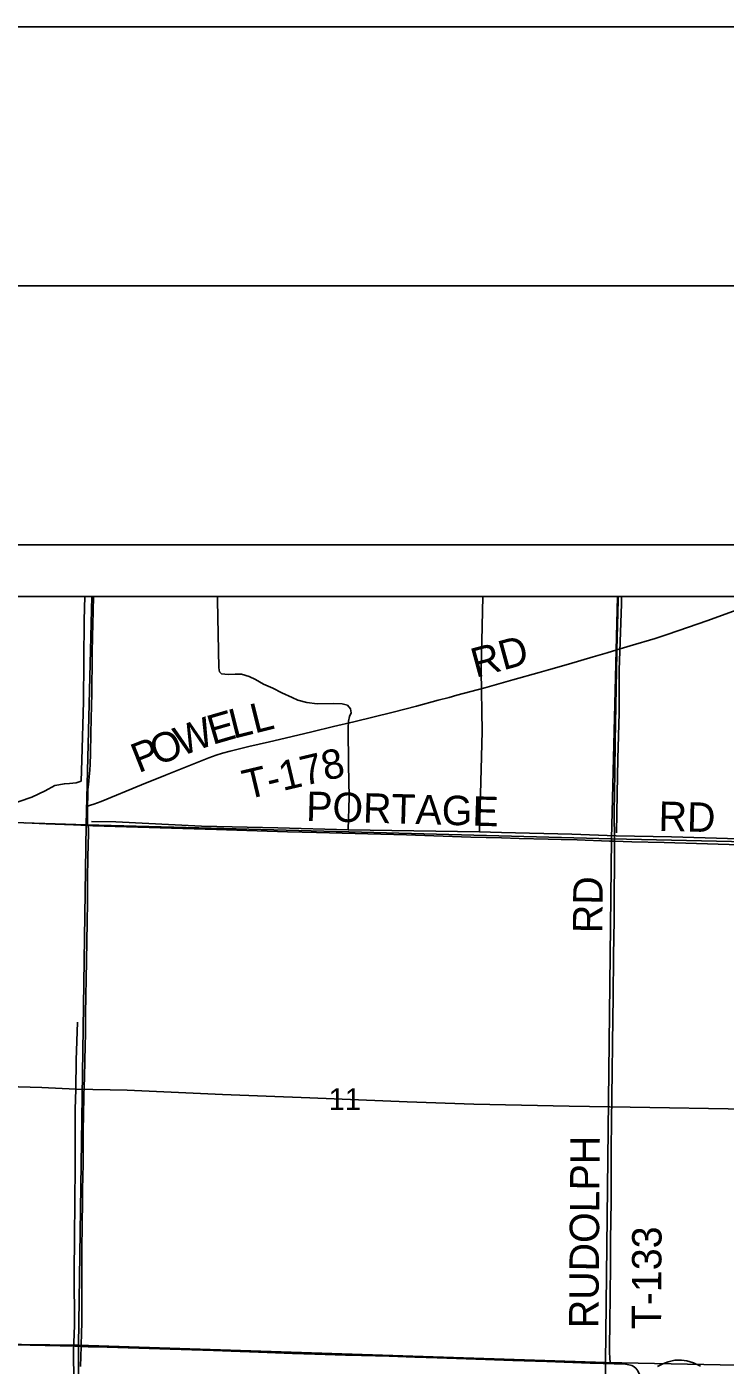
# Model space of a CAD drawing. Extents: x 0 to 39.4, y 0 to 22.
# Drawn here: x 3.277 to 4.625, y 19.416 to 22 of the extents above; entities that cross this region are included whole.
import ezdxf

# ---------------------------------------------------------------- set-up
doc = ezdxf.new("R2010")
doc.units = 0
for name, color, linetype in [('Default', 7, 'Continuous'), ('GM_X_Interstate_Route', 7, 'Continuous'), ('GM_X_Major_River', 7, 'Continuous'), ('GM_X_Minor_River', 7, 'Continuous'), ('GM_X_Section', 7, 'Continuous'), ('GM_X_Section_Text', 7, 'Continuous'), ('GM_X_Township_Road', 7, 'Continuous'), ('GM_X_Township_Road_Text', 7, 'Continuous'), ('SH_Border', 7, 'Continuous'), ('SH_Cut_Line', 7, 'Continuous'), ('SH_Data', 7, 'Continuous')]:
    doc.layers.add(name, color=color, linetype=linetype)

msp = doc.modelspace()

# ---------------------------------------------------------------- linework, layer by layer
at = {"layer": 'Default'}
for points in [[(3.4024, 20.9), (2.3931, 20.9), (2.3906, 20.4913), (3.3917, 20.4596)], [(4.4171, 20.9), (3.4024, 20.9), (3.3917, 20.4596), (4.4054, 20.4323)], [(5.4307, 20.9), (4.4171, 20.9), (4.4054, 20.4323), (5.4199, 20.4099)]]:
    msp.add_lwpolyline(points, close=True, dxfattribs=at)
at = {"layer": 'GM_X_Interstate_Route'}
msp.add_lwpolyline([(5.4327, 20.9), (2.1, 20.9)], dxfattribs=at)
at = {"layer": 'GM_X_Major_River'}
msp.add_lwpolyline([(4.5772, 19.4146), (4.5636, 19.4211), (4.5507, 19.4246), (4.5408, 19.4257), (4.5279, 19.4258), (4.515, 19.4228), (4.5048, 19.4186), (4.4941, 19.4137)], dxfattribs=at)
at = {"layer": 'GM_X_Minor_River'}
for points in [[(3.3893, 20.9), (3.3877, 20.8543), (3.3868, 20.6974), (3.3835, 20.5843), (3.3818, 20.544), (3.3723, 20.5406), (3.3594, 20.5391), (3.3496, 20.5388), (3.3313, 20.535), (3.3123, 20.5248), (3.2869, 20.5128), (3.2626, 20.5045), (3.2424, 20.4977), (3.228, 20.4905), (3.2071, 20.4769), (3.1965, 20.4762), (2.9935, 20.4806), (2.8319, 20.4845), (2.7583, 20.4866), (2.5868, 20.4939), (2.399, 20.4979)], [(3.8975, 20.4498), (3.8989, 20.5128), (3.8979, 20.5755), (3.897, 20.6469), (3.8978, 20.6594), (3.8997, 20.6682), (3.9028, 20.6754), (3.9017, 20.683), (3.8957, 20.6906), (3.8858, 20.6929), (3.8691, 20.6937), (3.8376, 20.693), (3.8175, 20.6958), (3.8004, 20.7), (3.7894, 20.705), (3.7693, 20.7145), (3.7519, 20.7229), (3.7341, 20.731), (3.7182, 20.7398), (3.7061, 20.7455), (3.6917, 20.7501), (3.6792, 20.7505), (3.6655, 20.7498), (3.6526, 20.751), (3.6488, 20.7548), (3.6477, 20.7624), (3.6451, 20.8934), (3.6452, 20.9)], [(4.1506, 20.4456), (4.1557, 20.6397), (4.1542, 20.7567), (4.157, 20.9)], [(4.425, 20.9), (4.4248, 20.8861), (4.4223, 20.8125), (4.4202, 20.7578), (4.4203, 20.6757), (4.4178, 20.5868), (4.4164, 20.5192), (4.415, 20.444)], [(5.0405, 20.629), (5.0417, 20.5162), (5.0429, 20.4182), (4.9063, 20.4236), (4.7159, 20.4302), (4.5213, 20.4361), (4.4146, 20.4383), (4.3289, 20.4412), (4.1931, 20.4443), (4.1506, 20.4456), (3.8975, 20.4498), (3.7617, 20.4536), (3.6141, 20.4571), (3.4491, 20.4655), (3.4017, 20.4657)], [(2.8819, 20.2127), (2.8805, 20.1337), (2.8805, 20.03), (2.8792, 19.9628), (2.9205, 19.9619), (3.0951, 19.9588), (3.2157, 19.955), (3.3064, 19.9524), (3.3716, 19.9492), (3.4706, 19.947), (3.655, 19.9389), (3.8234, 19.9323), (4.0109, 19.9245), (4.1395, 19.9203), (4.3235, 19.916), (4.4418, 19.9145), (4.6683, 19.9107), (4.8691, 19.9098), (4.9609, 19.9087), (5.0834, 19.9068), (5.1464, 19.9048), (5.2027, 19.9034)], [(3.3676, 19.3853), (3.367, 19.4425), (3.3691, 19.4938), (3.3686, 19.5948), (3.3692, 19.6632), (3.3704, 19.7995), (3.3707, 19.9101), (3.3716, 19.9492), (3.3726, 20.005), (3.3751, 20.0783)]]:
    msp.add_lwpolyline(points, dxfattribs=at)
at = {"layer": 'GM_X_Section'}
for points in [[(2.3906, 20.4913), (3.3917, 20.4596), (3.377, 19.4549), (2.7709, 19.4617), (2.3842, 19.4785)], [(3.3917, 20.4596), (4.4054, 20.4323), (4.394, 19.4215), (3.377, 19.4549)], [(4.4054, 20.4323), (5.4199, 20.4099), (5.4196, 20.3595), (5.4059, 19.4006), (4.394, 19.4215)], [(2.3842, 19.4785), (2.7709, 19.4617), (3.377, 19.4549), (3.3817, 18.4522), (2.3742, 18.4805)], [(3.377, 19.4549), (4.394, 19.4215), (4.3942, 18.4237), (3.3817, 18.4522)], [(4.394, 19.4215), (5.4059, 19.4006), (5.4065, 19.3604), (5.3953, 18.3924), (4.3942, 18.4237)]]:
    msp.add_lwpolyline(points, close=True, dxfattribs=at)
at = {"layer": 'GM_X_Township_Road'}
for points in [[(3.3945, 20.4952), (3.3945, 20.4963), (3.3948, 20.5151), (3.3952, 20.5268), (3.3959, 20.5371), (3.3974, 20.552), (3.3985, 20.565), (3.3992, 20.5768), (3.3999, 20.5967), (3.4008, 20.6364), (3.4021, 20.6905), (3.4025, 20.7117), (3.4028, 20.7347), (3.4032, 20.7632), (3.4035, 20.79), (3.4042, 20.8242), (3.4047, 20.8453), (3.4056, 20.9)], [(4.416, 20.7972), (4.4168, 20.8442), (4.4181, 20.8939), (4.4183, 20.9)], [(4.416, 20.7972), (4.4418, 20.8048), (4.4895, 20.8191), (4.5131, 20.8267), (4.5543, 20.8409), (4.5895, 20.8532), (4.6975, 20.8926), (4.7122, 20.8976), (4.7188, 20.9)], [(3.3945, 20.4952), (3.4003, 20.4971), (3.4062, 20.4991), (3.4207, 20.5046), (3.4984, 20.5364), (3.5445, 20.5551), (3.6282, 20.5885), (3.6428, 20.5939), (3.6546, 20.5977), (3.6696, 20.6017), (3.7059, 20.6105), (3.7453, 20.6194), (3.7755, 20.6266), (3.8269, 20.6388), (3.8692, 20.649), (3.9085, 20.6583), (3.984, 20.6768), (4.0291, 20.6884), (4.0711, 20.6998), (4.0922, 20.7052), (4.1071, 20.7095), (4.1611, 20.724), (4.2149, 20.7393), (4.2659, 20.7533), (4.2838, 20.7584), (4.3225, 20.7698), (4.3703, 20.7836), (4.3971, 20.7917), (4.416, 20.7972)], [(4.411, 20.4277), (4.4107, 20.4836), (4.4112, 20.5209), (4.4117, 20.5613), (4.4125, 20.6204), (4.4146, 20.7229), (4.4159, 20.7913), (4.416, 20.7972)], [(3.395, 20.458), (3.3945, 20.4606), (3.3942, 20.4622), (3.3941, 20.4632), (3.3941, 20.4642), (3.3945, 20.4952)], [(3.274, 20.4632), (3.3144, 20.4613), (3.3671, 20.4591), (3.395, 20.458)], [(3.3818, 19.4524), (3.3818, 19.4543), (3.3825, 19.4788), (3.383, 19.4976), (3.3833, 19.5056), (3.3832, 19.5392), (3.3834, 19.569), (3.3835, 19.6057), (3.3835, 19.6318), (3.384, 19.6952), (3.3844, 19.7254), (3.3849, 19.7579), (3.3852, 19.7773), (3.3857, 19.8071), (3.3858, 19.8189), (3.386, 19.8438), (3.386, 19.8718), (3.3863, 19.8972), (3.387, 19.9377), (3.3884, 19.9718), (3.3893, 20.0041), (3.3898, 20.0327), (3.3902, 20.0557), (3.3907, 20.0955), (3.3912, 20.1272), (3.3917, 20.1633), (3.3921, 20.195), (3.3929, 20.2366), (3.3934, 20.2683), (3.394, 20.3131), (3.3945, 20.3535), (3.3952, 20.3982), (3.3957, 20.4194), (3.3959, 20.443), (3.3959, 20.453), (3.3959, 20.4538), (3.3957, 20.4547), (3.3956, 20.4555), (3.395, 20.458)], [(3.395, 20.458), (3.4044, 20.4577), (3.6435, 20.4504), (3.7802, 20.4459), (3.8361, 20.4446), (3.9603, 20.4412), (4.01, 20.4398), (4.0628, 20.4381), (4.1342, 20.4358), (4.1932, 20.434), (4.2274, 20.4333), (4.2833, 20.4316), (4.3082, 20.4309), (4.3392, 20.4302), (4.4013, 20.428), (4.411, 20.4277)], [(4.4037, 19.4193), (4.4031, 19.4233), (4.4025, 19.4282), (4.4021, 19.4327), (4.4017, 19.439), (4.4018, 19.4545), (4.4024, 19.495), (4.4029, 19.554), (4.4033, 19.6069), (4.4038, 19.6566), (4.4042, 19.697), (4.4046, 19.7312), (4.4049, 19.7965), (4.4051, 19.8338), (4.4055, 19.8867), (4.4067, 19.983), (4.4072, 20.0359), (4.4079, 20.0856), (4.4085, 20.126), (4.4095, 20.2069), (4.4104, 20.2753), (4.4107, 20.3188), (4.4112, 20.3903), (4.411, 20.4277)], [(4.411, 20.4277), (4.4448, 20.4267), (4.5069, 20.425), (4.6529, 20.4205), (4.7492, 20.4177), (4.7926, 20.4164), (4.833, 20.4154), (4.9045, 20.4137), (4.9112, 20.4137)], [(2.3844, 19.4813), (2.3919, 19.4813), (2.4199, 19.4804), (2.4727, 19.4781), (2.5161, 19.4762), (2.572, 19.474), (2.6186, 19.4719), (2.6869, 19.469), (2.7801, 19.4654), (2.8453, 19.4635), (2.895, 19.4619), (2.9602, 19.4607), (2.9975, 19.46), (3.0348, 19.4594), (3.1249, 19.4576), (3.1684, 19.4567), (3.2088, 19.4559), (3.2834, 19.4546), (3.3704, 19.4527), (3.3818, 19.4524)], [(3.3806, 19.4139), (3.3818, 19.4524)], [(3.3818, 19.4524), (3.3958, 19.452), (3.4325, 19.451), (3.4729, 19.4499), (3.5537, 19.4471), (3.6375, 19.4445), (3.6717, 19.4435), (3.7245, 19.4415), (3.7897, 19.439), (3.8332, 19.4376), (3.8922, 19.4358), (3.9233, 19.4349), (3.9761, 19.4335), (4.0258, 19.4317), (4.0693, 19.4304), (4.1066, 19.4293), (4.1625, 19.4273), (4.2153, 19.4255), (4.2805, 19.4233), (4.3643, 19.4203), (4.3892, 19.4194), (4.4037, 19.4193)], [(4.4037, 19.4193), (4.4109, 19.4192), (4.4234, 19.4186), (4.4322, 19.418), (4.4388, 19.4171), (4.4419, 19.4165), (4.4448, 19.4155), (4.4476, 19.4141), (4.4501, 19.4123), (4.4524, 19.4103), (4.4544, 19.4079), (4.4561, 19.4053), (4.4577, 19.4024), (4.4606, 19.3968), (4.4629, 19.3922), (4.464, 19.3897), (4.4649, 19.3875)]]:
    msp.add_lwpolyline(points, dxfattribs=at)
at = {"layer": 'SH_Border'}
msp.add_lwpolyline([(1.5, 21.5), (33.5, 21.5), (33.5, 0.5), (1.5, 0.5)], close=True, dxfattribs=at)
at = {"layer": 'SH_Cut_Line'}
msp.add_lwpolyline([(0, 0), (34, 0), (34, 22), (0, 22)], close=True, dxfattribs=at)
at = {"layer": 'SH_Data'}
for p, q in [((2, 21), (9, 21)), ((2.1, 20.9), (8.9, 20.9))]:
    msp.add_line(p, q, dxfattribs=at)

# ---------------------------------------------------------------- texts
at = {"layer": 'GM_X_Section_Text'}
msp.add_text('11', height=0.04186, rotation=0, dxfattribs=at).set_placement((3.8597, 19.909))
at = {"layer": 'GM_X_Township_Road_Text'}
for s, height, rotation, p in [('RD', 0.05682, 15.2121, (4.1436, 20.743)), ('E', 0.0568, 16.1685, (3.6354, 20.6135)), ('L', 0.0568, 14.1308, (3.6757, 20.6252)), ('L', 0.0568, 14.0383, (3.7169, 20.6355)), ('W', 0.0568, 20.1211, (3.5746, 20.5911)), ('P', 0.0568, 21.512, (3.4927, 20.5589)), ('O', 0.0568, 21.5099, (3.5284, 20.5729)), ('T-178', 0.05682, 13.3683, (3.7012, 20.508)), ('PORTAGE', 0.05682, 358.3556, (3.8156, 20.4671)), ('RD', 0.05682, 358.5194, (4.4957, 20.4479)), ('RD', 0.05682, 89.5083, (4.3877, 20.2501)), ('RUDOLPH', 0.05682, 89.5669, (4.3802, 19.4874)), ('T-133', 0.05682, 89.7192, (4.5012, 19.4855))]:
    msp.add_text(s, height=height, rotation=rotation, dxfattribs=at).set_placement(p)

doc.saveas('drawing.dxf')
